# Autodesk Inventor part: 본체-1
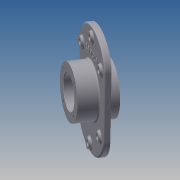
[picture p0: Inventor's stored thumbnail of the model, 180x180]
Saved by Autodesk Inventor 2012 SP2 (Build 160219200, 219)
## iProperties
Created: 2015-02
Part Number: 본체-1
Material: 알루미늄-6061
Document SubType Name: Modeling
Designer: Administrator
Density: 2.71 g/cm^3
Mass: 1662.1 g
Surface Area: 942.61 cm^2
Volume: 613.321 cm^3
Author: Administrator
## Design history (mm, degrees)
sketch "스케치1"
  geometry: L1 (-70, 60)-(70, 60); L2 (70, 60)-(70, -60); L3 (70, -60)-(-70, -60); L4 (-70, -60)-(-70, 60); L5 (-70, 0)-(70, 0); L6 (0, 60)-(0, 110); L7 (0, -60)-(0, -110); 1 further point; 4 other entities
  constraints: 15 end point, 4 midpoint, 3 horizontal, 2 parallel, 2 vertical, 1 horizontal alignment, 1 perpendicular, 1 vertical alignment, 18 other
  dimensions: "d10" = 120 distance of L1.end L2.end; "d11" = 140 distance of L1.start L1.end; "d16" = 50 distance of L6.start L6.end
extrude "돌출1" new body sketch "스케치1" distance "d17" = 12; taper "d18" = 0 deg
sketch "스케치2"
  geometry: C1 r 50 at (0, 0); 1 further point
  constraints: 1 centre point, 1 coincident
  dimensions: "d19" = 100 diameter of C1
extrude "돌출2" join sketch "스케치2" distance "d20" = 37; taper "d22" = 0 deg; dims "d21" = 33, "d23" = 0
hole "구멍1" diameter "d26" = 62; stored, may be unused: countersink angle "d30" = 90 deg, drill point angle "d32" = 0 deg; dims "d27" = 6, "d28" = 4, "d29" = 2, "d31" = 22, "d44" = 10, "d45" = 10
hole "구멍2" diameter "d35" = 62; stored, may be unused: countersink angle "d39" = 90 deg, drill point angle "d41" = 0 deg; dims "d36" = 6, "d37" = 4, "d38" = 2, "d40" = 22, "d42" = 10, "d43" = 10
hole "구멍3" diameter "d48" = 45; stored, may be unused: countersink angle "d52" = 90 deg, drill point angle "d54" = 118 deg; dims "d46" = 10, "d47" = 10, "d49" = 6, "d50" = 4, "d51" = 2, "d53" = 22
sketch "스케치3"
  geometry: L1 (60, -70)-(-60, -70) reference; L2 (-60, 70)-(60, 70) reference; L3 (60, -53)-(-60, -53); L4 (-60, 53)-(60, 53); C1 r 50 at (0, 0) reference; C2 r 10 at (-57.146, 53); C3 r 10 at (60, 53); C4 r 10 at (-57.146, -53); C5 r 10 at (60, -53); C6 r 10 at (93, 0); C7 r 10 at (-93, 0); 8 further points; 2 other entities
  constraints: 8 coincident, 6 centre point, 4 end point, 3 horizontal alignment, 3 parallel, 2 point on line, 1 vertical alignment, 10 other
  dimensions: "d55" = 17 distance between parallel lines of L2 L4; "d56" = 20 diameter of C2; "d57" = 20 diameter of C3; "d58" = 20 diameter of C4; "d59" = 20 diameter of C5; "d60" = 20 diameter of C6; "d61" = 20 diameter of C7
extrude "돌출3" join sketch "스케치3" distance "d62" = 5; taper "d63" = 0 deg
hole "구멍4" diameter "d66" = 11; stored, may be unused: countersink angle "d70" = 90 deg, drill point angle "d72" = 118 deg; dims "d64" = 10, "d65" = 10, "d67" = 6, "d68" = 4, "d69" = 2, "d71" = 22
hole "구멍5" diameter "d75" = 11; stored, may be unused: countersink angle "d79" = 90 deg, drill point angle "d81" = 118 deg; dims "d73" = 10, "d74" = 10, "d76" = 6, "d77" = 4, "d78" = 2, "d80" = 22
hole "구멍6" diameter "d84" = 11; stored, may be unused: countersink angle "d88" = 90 deg, drill point angle "d90" = 118 deg; dims "d82" = 10, "d83" = 10, "d85" = 6, "d86" = 4, "d87" = 2, "d89" = 22
hole "구멍7" diameter "d93" = 11; stored, may be unused: countersink angle "d97" = 90 deg, drill point angle "d99" = 118 deg; dims "d91" = 10, "d92" = 10, "d94" = 6, "d95" = 4, "d96" = 2, "d98" = 22
hole "구멍8" diameter "d102" = 11; stored, may be unused: countersink angle "d106" = 90 deg, drill point angle "d108" = 118 deg; dims "d100" = 10, "d101" = 10, "d103" = 6, "d104" = 4, "d105" = 2, "d107" = 22
hole "구멍9" diameter "d111" = 11; stored, may be unused: countersink angle "d115" = 90 deg, drill point angle "d117" = 118 deg; dims "d109" = 10, "d110" = 10, "d112" = 6, "d113" = 4, "d114" = 2, "d116" = 22
sketch "스케치4"
  geometry: L1 (0, 0)-(41, 0); L2 (0, 0)-(28.991, -28.991); L3 (0, 0)-(28.991, 28.991); L4 (0, 0)-(-28.991, 28.991); L5 (0, 0)-(-28.991, -28.991); C1 r 31 at (0, 0) reference; A1 r 41 centre (0, 0) between (41, 0) and (28.991, -28.991); 4 further points
  constraints: 10 end point, 5 coincident, 2 point on circle, 1 centre point, 1 horizontal, 17 other
  dimensions: "d118" = 82 diameter of A1; "d119" = 45 deg angle of L1 L2; "d122" = 360 deg dimension on C1.centre L2.end (derived)
hole "구멍10" sketch "스케치4" at (28.991, -28.991), (28.991, 28.991), (-28.991, 28.991), (-28.991, -28.991) diameter "d124" = 4.917; stored, may be unused: countersink angle "d128" = 90 deg, drill point angle "d130" = 118 deg; dims "d125" = 10, "d126" = 4, "d127" = 2, "d129" = 13
sketch "스케치5"
  geometry: L1 (0, 0)-(-41, 0); L2 (0, 0)-(-28.991, -28.991); L3 (0, 0)-(28.991, -28.991); L4 (0, 0)-(28.991, 28.991); L5 (0, 0)-(-28.991, 28.991); C1 r 31 at (0, 0) reference; A1 r 41 centre (0, 0) between (-41, 0) and (-28.991, -28.991); 4 further points
  constraints: 10 end point, 5 coincident, 2 point on circle, 1 centre point, 1 horizontal, 17 other
  dimensions: "d131" = 82 diameter of A1; "d132" = 45 deg angle of L2 L1; "d135" = 360 deg dimension on C1.centre L2.end (derived)
hole "구멍11" sketch "스케치5" at (-28.991, -28.991), (28.991, -28.991), (28.991, 28.991), (-28.991, 28.991) diameter "d137" = 4.917; stored, may be unused: countersink angle "d141" = 90 deg, drill point angle "d143" = 118 deg; dims "d138" = 10, "d139" = 4, "d140" = 2, "d142" = 13
fillet "모깎기1" dims "d144" = 3
chamfer "모따기1" distance "d145" = 1; stored, may be unused: second distance "d146" = 2, angle "d147" = 45 deg
fillet "모깎기2" dims "d148" = 0.3
sketch "스케치6"
  geometry: C1 r 13 at (93, 0) reference; C2 r 53 at (0, 0) reference; 1 further point
  constraints: 1 horizontal alignment, 1 other
  dimensions: "d149" = 65 distance of point (65, 0) C2.centre
feature "엠보싱1" sketch "스케치6" dims "d10" = 120, "d40" = 22, "d150" = 1, "d151" = 0
node "솔리드1"
